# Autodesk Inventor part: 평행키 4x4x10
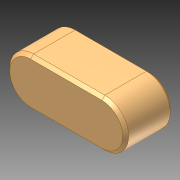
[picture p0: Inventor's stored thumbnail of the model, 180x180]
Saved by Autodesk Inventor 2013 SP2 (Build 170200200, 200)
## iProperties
Created: 2025-04
Part Number: 평행키 4x4x10
Material: Generic
Document SubType Name: Modeling
Designer: 601
Density: 1 g/cm^3
Author: 601
변환 표준: STEP AP214IS
전처리기: Build: 200, Release: 2013 SP2 Update 6 - Date: Thu 07/17/2014
전송 단위: 밀리미터
불확실성: 0.01
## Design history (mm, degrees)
node "평행키 4x4x101"
body "Solid1"
node "기준1"
